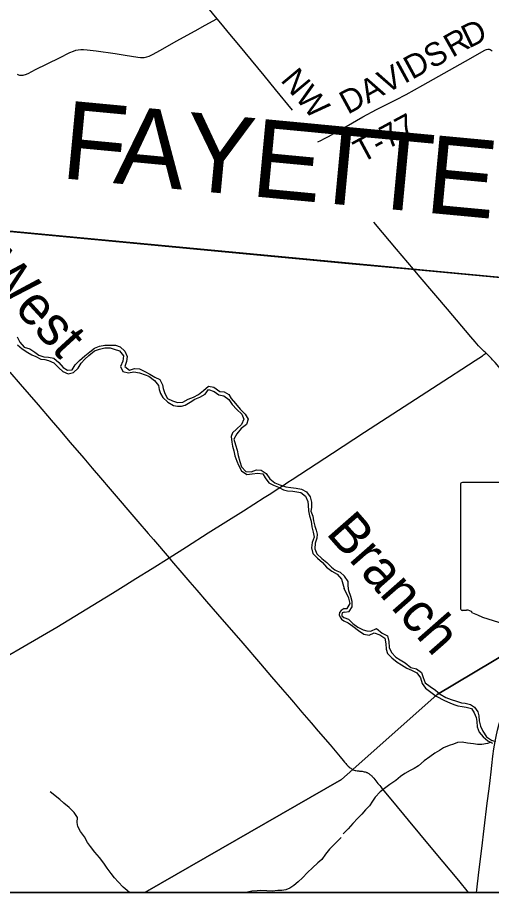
# Model space of a CAD drawing. Extents: x -49 to -8.2, y 9.4 to 23.5.
# Drawn here: x -41.83 to -41.255, y 14.204 to 15.267 of the extents above; entities that cross this region are included whole.
import ezdxf

# ---------------------------------------------------------------- set-up
doc = ezdxf.new("R2010")
doc.units = 0
for name, color, linetype in [('GM_X_Adjacent_County', 7, 'Continuous'), ('GM_X_Adjacent_County_Text', 7, 'Continuous'), ('GM_X_County_Road', 7, 'Continuous'), ('GM_X_County_Road_Text', 7, 'Continuous'), ('GM_X_Minor_River', 7, 'Continuous'), ('GM_X_Minor_River_Text', 7, 'Continuous'), ('GM_X_State_Route', 7, 'Continuous'), ('GM_X_State_Shield', 7, 'Continuous'), ('GM_X_Township', 7, 'Continuous'), ('GM_X_Township_Road', 7, 'Continuous'), ('GM_X_Township_Road_Text', 7, 'Continuous')]:
    doc.layers.add(name, color=color, linetype=linetype)

msp = doc.modelspace()

# ---------------------------------------------------------------- linework, layer by layer
at = {"layer": 'GM_X_Adjacent_County'}
for points in [[(-39.4895, 17.0861), (-39.4895, 14.2039), (-46.2895, 14.2039), (-46.2895, 15.4273)], [(-40.1912, 14.2039), (-40.1354, 14.8465), (-42.6345, 15.0821)]]:
    msp.add_lwpolyline(points, dxfattribs=at)
at = {"layer": 'GM_X_County_Road'}
for points in [[(-41.5879, 15.2654), (-41.5992, 15.279), (-41.6289, 15.315), (-41.6565, 15.3486), (-41.6676, 15.3621)], [(-41.4965, 15.1542), (-41.5172, 15.1794), (-41.531, 15.1963), (-41.5615, 15.2335), (-41.5744, 15.2491), (-41.5813, 15.2575), (-41.5879, 15.2654)], [(-41.3497, 14.961), (-41.3703, 14.9853), (-41.3874, 15.0055), (-41.398, 15.0181)]]:
    msp.add_lwpolyline(points, dxfattribs=at)
at = {"layer": 'GM_X_Minor_River'}
for points in [[(-41.8309, 14.8788), (-41.8273, 14.8723), (-41.8221, 14.8665), (-41.8154, 14.8642), (-41.8094, 14.8605), (-41.8043, 14.8568), (-41.7982, 14.8547), (-41.7925, 14.8544), (-41.786, 14.8532), (-41.78, 14.8479), (-41.7747, 14.8417), (-41.7698, 14.8384), (-41.7639, 14.839), (-41.7602, 14.845), (-41.7552, 14.8503), (-41.7485, 14.8559), (-41.7427, 14.8608), (-41.737, 14.8651), (-41.7307, 14.8675), (-41.7242, 14.869), (-41.7114, 14.8689), (-41.7057, 14.8667), (-41.7002, 14.8617), (-41.6971, 14.8552), (-41.6981, 14.8488), (-41.6999, 14.8427), (-41.6944, 14.8383), (-41.6883, 14.8403), (-41.6824, 14.8399), (-41.6757, 14.8368), (-41.6697, 14.8335), (-41.6638, 14.83), (-41.6574, 14.8269), (-41.6542, 14.8208), (-41.6533, 14.816), (-41.6516, 14.8099), (-41.6483, 14.804), (-41.6422, 14.8011), (-41.6359, 14.799), (-41.6296, 14.7997), (-41.6231, 14.8032), (-41.6168, 14.8058), (-41.6105, 14.8088), (-41.6047, 14.8139), (-41.5984, 14.8189), (-41.5918, 14.8177), (-41.5848, 14.8127), (-41.5794, 14.8123), (-41.5736, 14.8088), (-41.5708, 14.8039), (-41.5659, 14.7979), (-41.5602, 14.7912), (-41.554, 14.7851), (-41.5503, 14.7788), (-41.5524, 14.7725), (-41.5589, 14.7676), (-41.5642, 14.761), (-41.5676, 14.7546), (-41.5658, 14.7479), (-41.5638, 14.7412), (-41.5625, 14.7348), (-41.5605, 14.7273), (-41.5583, 14.7212), (-41.5532, 14.7153), (-41.5465, 14.7148), (-41.5402, 14.7172), (-41.5345, 14.717), (-41.5286, 14.7131), (-41.524, 14.7066), (-41.5179, 14.7014), (-41.5117, 14.6991), (-41.5046, 14.6969), (-41.4987, 14.6961), (-41.4919, 14.6951)], [(-41.8304, 14.8691), (-41.8248, 14.8642), (-41.8179, 14.86), (-41.813, 14.8571), (-41.8081, 14.8552), (-41.802, 14.8517), (-41.7973, 14.8512), (-41.7925, 14.8503), (-41.7861, 14.8475), (-41.7802, 14.8414), (-41.7751, 14.837), (-41.7687, 14.8341), (-41.7624, 14.8355), (-41.7568, 14.8408), (-41.753, 14.847), (-41.7485, 14.8519), (-41.7437, 14.8564), (-41.737, 14.8619), (-41.7307, 14.8639), (-41.7244, 14.8656), (-41.7179, 14.8657), (-41.7128, 14.864), (-41.7065, 14.862), (-41.7016, 14.8557), (-41.7025, 14.8494), (-41.7052, 14.843), (-41.7024, 14.8367), (-41.6956, 14.8351), (-41.6891, 14.8365), (-41.6822, 14.8351), (-41.6754, 14.8328), (-41.6707, 14.831), (-41.6639, 14.826), (-41.6593, 14.8197), (-41.6583, 14.8149), (-41.6568, 14.8102), (-41.654, 14.8052), (-41.6479, 14.7996), (-41.6409, 14.7954), (-41.6362, 14.7948), (-41.6314, 14.7947), (-41.6266, 14.7958), (-41.6209, 14.7994), (-41.6149, 14.8033), (-41.609, 14.8057), (-41.6027, 14.8093), (-41.5985, 14.8148), (-41.5916, 14.8126), (-41.5861, 14.8086), (-41.5797, 14.8074), (-41.5736, 14.8027), (-41.5699, 14.7966), (-41.5642, 14.7907), (-41.5582, 14.7849), (-41.5556, 14.779), (-41.5583, 14.7724), (-41.5643, 14.7669), (-41.5695, 14.7624), (-41.5709, 14.7577), (-41.5703, 14.751), (-41.5693, 14.7462), (-41.5678, 14.7405), (-41.5667, 14.7342), (-41.5641, 14.7279), (-41.5621, 14.723), (-41.5583, 14.7161), (-41.5521, 14.7116), (-41.5456, 14.7123), (-41.5387, 14.7134), (-41.5327, 14.7124), (-41.5297, 14.7076), (-41.5253, 14.7015)], [(-41.5253, 14.7015), (-41.5195, 14.6986), (-41.5134, 14.6965), (-41.5073, 14.693), (-41.5026, 14.6918), (-41.4961, 14.6913), (-41.4914, 14.6907), (-41.4866, 14.6899), (-41.4808, 14.6853), (-41.4778, 14.679), (-41.4776, 14.6743), (-41.4773, 14.6676), (-41.4757, 14.6615), (-41.4738, 14.655), (-41.4731, 14.6483), (-41.4715, 14.6417), (-41.4702, 14.6356), (-41.4728, 14.6291), (-41.4736, 14.6227), (-41.4717, 14.6158), (-41.4663, 14.6099), (-41.4602, 14.6047), (-41.4552, 14.5993), (-41.4489, 14.5943), (-41.4425, 14.5906), (-41.4372, 14.5847), (-41.4337, 14.5732)], [(-41.4919, 14.6951), (-41.4856, 14.6937), (-41.4796, 14.6908), (-41.475, 14.6847), (-41.4734, 14.678), (-41.4735, 14.6717), (-41.4741, 14.667), (-41.472, 14.6611), (-41.4712, 14.6554), (-41.4695, 14.6491), (-41.4678, 14.6439), (-41.4667, 14.6392), (-41.4668, 14.6344), (-41.4691, 14.6283), (-41.4696, 14.6215), (-41.4668, 14.6152), (-41.461, 14.6096), (-41.4549, 14.6048), (-41.4493, 14.5993), (-41.4451, 14.596)], [(-41.4451, 14.596), (-41.4428, 14.5948), (-41.4385, 14.5929), (-41.4335, 14.588)], [(-41.434, 14.5444), (-41.4278, 14.5451), (-41.4241, 14.5511), (-41.4242, 14.5576), (-41.4256, 14.5635), (-41.4282, 14.5705), (-41.429, 14.5766), (-41.4288, 14.5816), (-41.4335, 14.588)], [(-41.434, 14.5488), (-41.43, 14.5491), (-41.4267, 14.5551), (-41.4283, 14.5616), (-41.4337, 14.5732)], [(-41.434, 14.5488), (-41.4374, 14.5465), (-41.4393, 14.544), (-41.4398, 14.5412), (-41.4388, 14.5383), (-41.4369, 14.5358), (-41.4342, 14.5338)], [(-41.434, 14.5444), (-41.4363, 14.5436), (-41.4367, 14.5415), (-41.4365, 14.54), (-41.4341, 14.5378)], [(-41.4342, 14.5338), (-41.4289, 14.5316), (-41.4232, 14.5276), (-41.4165, 14.5223), (-41.4101, 14.5179), (-41.4036, 14.5164), (-41.3975, 14.5194), (-41.3907, 14.5168), (-41.3846, 14.5129), (-41.3834, 14.5059), (-41.3829, 14.4994), (-41.3813, 14.4941), (-41.376, 14.4889), (-41.3696, 14.4839), (-41.3643, 14.4804), (-41.3577, 14.4765), (-41.3519, 14.4741), (-41.3456, 14.4706), (-41.3412, 14.4645), (-41.3393, 14.458), (-41.3352, 14.4522), (-41.3285, 14.4472), (-41.3221, 14.4425), (-41.3122, 14.4371), (-41.3056, 14.4343), (-41.3007, 14.4322), (-41.2958, 14.4306), (-41.2906, 14.4297), (-41.2857, 14.4291), (-41.2794, 14.4273), (-41.2761, 14.4223), (-41.2735, 14.4164), (-41.2728, 14.4116), (-41.2725, 14.405), (-41.27, 14.3985), (-41.2653, 14.3929), (-41.2596, 14.3883), (-41.2536, 14.3855)], [(-41.4341, 14.5378), (-41.4285, 14.5358), (-41.4232, 14.5308), (-41.4172, 14.5263), (-41.4109, 14.523), (-41.4062, 14.5216), (-41.4013, 14.5214), (-41.3944, 14.5247), (-41.3878, 14.5191), (-41.3813, 14.5158), (-41.3797, 14.5087), (-41.3793, 14.5017), (-41.3763, 14.4954), (-41.3709, 14.4896), (-41.3658, 14.4867), (-41.3597, 14.483), (-41.3528, 14.4774), (-41.3461, 14.4756), (-41.3401, 14.4713), (-41.3379, 14.465), (-41.3355, 14.4587), (-41.3295, 14.4542), (-41.3229, 14.4498), (-41.3171, 14.4448), (-41.3105, 14.4407), (-41.304, 14.4383), (-41.2976, 14.4363), (-41.2915, 14.4343), (-41.2868, 14.4341), (-41.2805, 14.4323), (-41.2756, 14.429), (-41.2715, 14.4234), (-41.2704, 14.4186), (-41.2699, 14.4126), (-41.2683, 14.4059), (-41.2654, 14.3998), (-41.2611, 14.3932), (-41.2551, 14.3888), (-41.2501, 14.3872)], [(-41.2554, 14.3864), (-41.2597, 14.3849), (-41.2666, 14.3836), (-41.2721, 14.3837), (-41.277, 14.3844), (-41.284, 14.3854), (-41.2905, 14.3864), (-41.2962, 14.3861), (-41.3012, 14.3841), (-41.3062, 14.3823), (-41.3131, 14.3795), (-41.3179, 14.3766), (-41.3236, 14.3732), (-41.3298, 14.3686), (-41.3367, 14.3639), (-41.3436, 14.3579), (-41.349, 14.3544), (-41.3538, 14.352), (-41.36, 14.3483), (-41.3653, 14.3448), (-41.3711, 14.3401), (-41.3782, 14.3353), (-41.385, 14.3304), (-41.39, 14.3261), (-41.396, 14.3199), (-41.3993, 14.3149), (-41.4032, 14.3092), (-41.408, 14.3044), (-41.4123, 14.2991), (-41.4171, 14.2942), (-41.4231, 14.2879), (-41.4289, 14.2811), (-41.4351, 14.2751)], [(-41.6944, 14.2039), (-41.697, 14.2063), (-41.7021, 14.2105), (-41.7081, 14.217), (-41.7125, 14.2218), (-41.7166, 14.227), (-41.7213, 14.2333), (-41.7256, 14.2395), (-41.7307, 14.2463), (-41.7365, 14.2529), (-41.7418, 14.2596), (-41.7454, 14.2645), (-41.7489, 14.2716), (-41.7538, 14.2781), (-41.757, 14.2839), (-41.7577, 14.2888), (-41.7574, 14.2949), (-41.7614, 14.301), (-41.7674, 14.3072), (-41.774, 14.3124), (-41.7791, 14.3168), (-41.7908, 14.3264)], [(-41.4374, 14.2706), (-41.442, 14.2664), (-41.4466, 14.2615), (-41.4516, 14.2565), (-41.4564, 14.2506), (-41.4609, 14.2442), (-41.4657, 14.2399), (-41.4724, 14.234), (-41.4784, 14.2282), (-41.4845, 14.2218), (-41.4897, 14.2167), (-41.4949, 14.2124), (-41.4999, 14.2092), (-41.5047, 14.2073), (-41.5094, 14.2064), (-41.5144, 14.2063), (-41.5211, 14.2056), (-41.5275, 14.206), (-41.5348, 14.2065), (-41.5395, 14.2061), (-41.5458, 14.2056), (-41.551, 14.2045), (-41.5538, 14.2039)]]:
    msp.add_lwpolyline(points, dxfattribs=at)
at = {"layer": 'GM_X_State_Route'}
for points in [[(-41.258, 14.3297), (-41.2568, 14.3401), (-41.2555, 14.3506), (-41.2546, 14.358), (-41.2534, 14.3694), (-41.2521, 14.3786), (-41.2507, 14.3872), (-41.2495, 14.3936), (-41.2477, 14.4011), (-41.2457, 14.4089), (-41.2446, 14.4128), (-41.2436, 14.4164), (-41.2409, 14.4243), (-41.2333, 14.4454)], [(-41.2733, 14.2039), (-41.2729, 14.2071), (-41.2703, 14.2287), (-41.2669, 14.2574), (-41.2639, 14.2818), (-41.2601, 14.3126), (-41.258, 14.3297)]]:
    msp.add_lwpolyline(points, dxfattribs=at)
at = {"layer": 'GM_X_State_Shield'}
for p, q in [((-41.2179, 14.7019), (-41.2903, 14.7019)), ((-41.2927, 14.6993), (-41.2927, 14.5493))]:
    msp.add_line(p, q, dxfattribs=at)
for centre, major_axis, start_param, end_param in [((-41.2899, 14.6997), (0.00286, 0), 1.712693, 3.28349), ((-41.2899, 14.5489), (0.00289, 0), 3.00124, 4.508301), ((-41.2894, 14.5643), (0.022, 0), 4.665946, 4.897461), ((-41.2849, 14.5406), (0.00795, 0), 0.519207, 1.627899), ((-41.1846, 14.6754), (0.1893, 0), 4.195997, 4.488961)]:
    msp.add_ellipse(centre, major_axis=major_axis, ratio=0.8, start_param=start_param, end_param=end_param, dxfattribs=at)
at = {"layer": 'GM_X_Township'}
for p, q in [((-44.8206, 14.2039), (-41.6759, 14.2039)), ((-41.6759, 14.2039), (-40.1912, 14.2039))]:
    msp.add_line(p, q, dxfattribs=at)
for points in [[(-40.5882, 17.1244), (-40.7343, 17.1261), (-41.0788, 17.1371), (-41.3573, 17.1515), (-41.4235, 17.1561), (-41.919, 17.2861), (-42.4235, 17.4155), (-42.4307, 17.336), (-42.4779, 16.8137), (-42.4838, 16.7488), (-42.5164, 16.3973), (-42.5481, 16.0375), (-42.5821, 15.6616), (-42.6063, 15.3944), (-42.6345, 15.0821), (-42.5793, 15.0769), (-42.3443, 15.0547), (-41.4287, 14.9682), (-41.3564, 14.9614), (-41.0499, 14.9326), (-40.8503, 14.9138), (-40.6501, 14.895)], [(-41.6759, 14.2039), (-41.4369, 14.3413), (-41.4231, 14.3535), (-41.3209, 14.4444), (-41.2078, 14.512), (-40.9525, 14.6647), (-40.8419, 14.7281), (-40.7347, 14.8098), (-40.6501, 14.895), (-40.8503, 14.9138), (-41.0499, 14.9326), (-41.3564, 14.9614), (-41.4287, 14.9682), (-42.3443, 15.0547), (-42.5793, 15.0769), (-42.6345, 15.0821), (-43.168, 15.1318), (-43.3434, 15.1483), (-43.7172, 15.1832), (-43.8792, 15.1984), (-44.0636, 15.2153), (-44.1589, 15.0879), (-44.8206, 14.2039)], [(-40.1912, 14.2039), (-40.1354, 14.8465), (-40.6501, 14.895), (-40.7347, 14.8098), (-40.8419, 14.7281), (-40.9525, 14.6647), (-41.2078, 14.512), (-41.3209, 14.4444), (-41.4231, 14.3535), (-41.4369, 14.3413), (-41.6759, 14.2039)]]:
    msp.add_lwpolyline(points, dxfattribs=at)
at = {"layer": 'GM_X_Township_Road'}
for points in [[(-41.8305, 15.1981), (-41.8292, 15.1973), (-41.8278, 15.1968), (-41.8264, 15.1966), (-41.825, 15.1967), (-41.8235, 15.1969), (-41.8221, 15.1972), (-41.8205, 15.1977), (-41.8175, 15.199), (-41.8083, 15.2036), (-41.7793, 15.218), (-41.7668, 15.2242), (-41.7625, 15.2261), (-41.7596, 15.227), (-41.7565, 15.2277), (-41.7534, 15.2279), (-41.7503, 15.2279), (-41.7457, 15.2275), (-41.7349, 15.2263), (-41.7118, 15.2232), (-41.6995, 15.2212), (-41.6842, 15.2185), (-41.6811, 15.2182), (-41.6795, 15.2181), (-41.678, 15.2182), (-41.6764, 15.2183), (-41.6749, 15.2186), (-41.6734, 15.219), (-41.6705, 15.22), (-41.6663, 15.2221), (-41.6568, 15.2273), (-41.6377, 15.2379), (-41.6146, 15.2507), (-41.6024, 15.2575), (-41.5884, 15.2652), (-41.5879, 15.2654)], [(-41.4659, 15.1159), (-41.4621, 15.1176), (-41.4578, 15.1197), (-41.453, 15.1223), (-41.4313, 15.1346), (-41.4111, 15.1461), (-41.3946, 15.155), (-41.3865, 15.1593), (-41.3711, 15.167), (-41.3587, 15.1735), (-41.3383, 15.1848), (-41.3126, 15.1992), (-41.28, 15.2175), (-41.2638, 15.2268), (-41.2624, 15.2275), (-41.261, 15.2281), (-41.2595, 15.2285), (-41.258, 15.2285), (-41.2565, 15.2281), (-41.2552, 15.2273), (-41.254, 15.2262)], [(-41.2616, 14.859), (-41.2628, 14.8601), (-41.2639, 14.8612), (-41.267, 14.8643), (-41.2691, 14.8664), (-41.2707, 14.8681), (-41.2726, 14.8703), (-41.2749, 14.8729), (-41.2802, 14.879), (-41.3085, 14.9124), (-41.3225, 14.929), (-41.3439, 14.9543), (-41.3497, 14.961)], [(-41.6463, 14.6104), (-41.6253, 14.6237), (-41.5989, 14.6407), (-41.5561, 14.6677), (-41.5309, 14.6838), (-41.523, 14.6888), (-41.5165, 14.6929), (-41.5119, 14.696), (-41.5079, 14.6985), (-41.5022, 14.7023), (-41.4969, 14.7057), (-41.4481, 14.7377), (-41.409, 14.763), (-41.3403, 14.8077), (-41.3267, 14.8166), (-41.3059, 14.8301), (-41.291, 14.8397), (-41.2749, 14.8503), (-41.266, 14.856), (-41.2646, 14.8569), (-41.2635, 14.8577), (-41.2623, 14.8585), (-41.2616, 14.859)], [(-41.1353, 14.7104), (-41.1364, 14.7112), (-41.1373, 14.7118), (-41.1379, 14.7124), (-41.1386, 14.713), (-41.1394, 14.7139), (-41.1413, 14.7162), (-41.1446, 14.7201), (-41.1643, 14.7437), (-41.1817, 14.7648), (-41.1972, 14.7834), (-41.2204, 14.8113), (-41.2344, 14.8284), (-41.2483, 14.8451), (-41.2505, 14.8476), (-41.2524, 14.8498), (-41.2536, 14.8511), (-41.2549, 14.8525), (-41.2559, 14.8536), (-41.257, 14.8547), (-41.2585, 14.8561), (-41.26, 14.8574), (-41.2616, 14.859)], [(-41.8397, 14.8359), (-41.8271, 14.8214), (-41.8054, 14.7962), (-41.7894, 14.7775), (-41.7791, 14.7655), (-41.7664, 14.7507), (-41.7498, 14.7314), (-41.7395, 14.7193), (-41.7296, 14.7077), (-41.7179, 14.694), (-41.6843, 14.6548), (-41.6717, 14.6399), (-41.6654, 14.6326), (-41.6463, 14.6104)], [(-41.8446, 14.4901), (-41.8224, 14.5031), (-41.7827, 14.5264), (-41.7607, 14.5398), (-41.7315, 14.5576), (-41.7151, 14.5676), (-41.6987, 14.5777), (-41.6865, 14.5852), (-41.667, 14.5974), (-41.6463, 14.6104)], [(-41.6463, 14.6104), (-41.6433, 14.6069), (-41.6307, 14.5924), (-41.621, 14.5811), (-41.6125, 14.5712), (-41.6008, 14.5574), (-41.5876, 14.5421), (-41.557, 14.5066), (-41.5354, 14.4817), (-41.5221, 14.4661), (-41.5087, 14.4506), (-41.5003, 14.4406), (-41.4954, 14.435), (-41.485, 14.423), (-41.4739, 14.4101), (-41.4652, 14.3999), (-41.4508, 14.3832), (-41.4386, 14.3687), (-41.435, 14.3643), (-41.4334, 14.3624), (-41.4319, 14.3606), (-41.4311, 14.3596), (-41.4302, 14.3586), (-41.4293, 14.3577), (-41.4283, 14.3568), (-41.4276, 14.3561), (-41.4266, 14.3554), (-41.4258, 14.3548), (-41.425, 14.3543), (-41.4237, 14.3536), (-41.4227, 14.3531), (-41.4216, 14.3527), (-41.4205, 14.3523)], [(-41.4205, 14.3523), (-41.4195, 14.3521), (-41.4182, 14.3519), (-41.4172, 14.3517), (-41.416, 14.3516), (-41.4151, 14.3515), (-41.414, 14.3514), (-41.413, 14.3513), (-41.412, 14.3512), (-41.4108, 14.351), (-41.4096, 14.3507), (-41.4084, 14.3504), (-41.4072, 14.35), (-41.4066, 14.3498), (-41.4059, 14.3495), (-41.4053, 14.3492), (-41.4047, 14.3488), (-41.4039, 14.3483), (-41.4033, 14.3479), (-41.4026, 14.3473), (-41.4017, 14.3467), (-41.4011, 14.3461), (-41.4004, 14.3455), (-41.3997, 14.3448), (-41.3989, 14.344), (-41.3979, 14.3428), (-41.3967, 14.3413), (-41.3953, 14.3396), (-41.3928, 14.3364), (-41.3907, 14.3338), (-41.3895, 14.3323), (-41.3876, 14.3299), (-41.3753, 14.315), (-41.356, 14.2919), (-41.3422, 14.2751), (-41.3246, 14.2538), (-41.2952, 14.2184), (-41.2832, 14.2039)]]:
    msp.add_lwpolyline(points, dxfattribs=at)

# ---------------------------------------------------------------- texts
at = {"layer": 'GM_X_Adjacent_County_Text'}
for s, rotation, p in [('F', 354.6034, (-41.7788, 15.0718)), ('A', 354.6034, (-41.7148, 15.0657)), ('Y', 354.6034, (-41.6315, 15.0579)), ('E', 354.6067, (-41.5483, 15.05)), ('T', 354.616, (-41.4779, 15.0433)), ('T', 354.6233, (-41.4075, 15.0367)), ('E', 354.6309, (-41.3371, 15.0301))]:
    msp.add_text(s, height=0.0947, rotation=rotation, dxfattribs=at).set_placement(p)
at = {"layer": 'GM_X_County_Road_Text'}
msp.add_text('NW', height=0.02841, rotation=309.8082, dxfattribs=at).set_placement((-41.5119, 15.1903))
at = {"layer": 'GM_X_Minor_River_Text'}
for s, rotation, p in [('West', 312.5562, (-41.8757, 14.9567)), ('Branch', 311.2768, (-41.4569, 14.64))]:
    msp.add_text(s, height=0.04735, rotation=rotation, dxfattribs=at).set_placement(p)
at = {"layer": 'GM_X_Township_Road_Text'}
for s, height, rotation, p in [('D', 0.0284, 25.8662, (-41.2826, 15.229)), ('R', 0.0284, 29.5091, (-41.3025, 15.2177)), ('DAVIDS', 0.02841, 28.5256, (-41.4294, 15.1486)), ('T-77', 0.02841, 28.3459, (-41.4124, 15.0896))]:
    msp.add_text(s, height=height, rotation=rotation, dxfattribs=at).set_placement(p)

doc.saveas('drawing.dxf')
